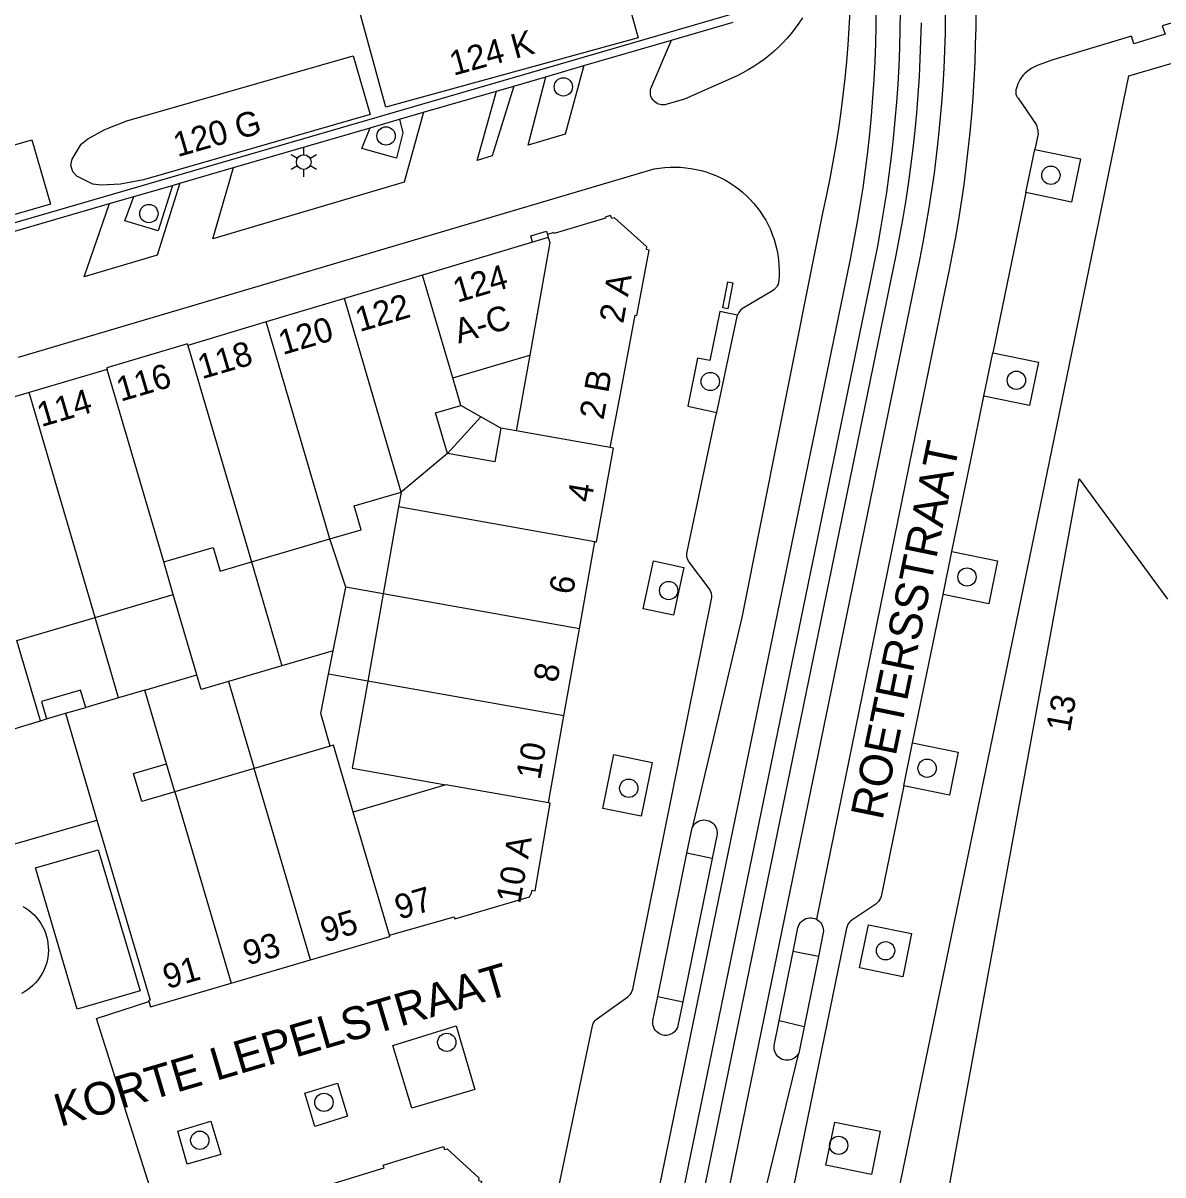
# Model space of a CAD drawing. Extents: x 122462 to 123306, y 485548 to 486417.
# Drawn here: x 122505.2 to 122575, y 486288.9 to 486359.4 of the extents above; entities that cross this region are included whole.
import ezdxf

# ---------------------------------------------------------------- set-up
doc = ezdxf.new("R2010")
doc.units = 0
for name, color, linetype in [('B-WE-IE-MEUBILAIR_WEGMEUBILAIR_VERKEERSBORD-S', 7, 'Continuous'), ('Level 1', 7, 'Continuous'), ('Level 12', 7, 'Continuous'), ('Level 15', 7, 'Continuous'), ('Level 17', 7, 'Continuous'), ('Level 19', 7, 'Continuous'), ('Level 22', 7, 'Continuous'), ('Level 37', 7, 'Continuous'), ('Level 4', 7, 'Continuous'), ('Level 40', 7, 'Continuous'), ('Level 50', 7, 'Continuous'), ('Level 53', 7, 'Continuous'), ('N werkgrens', 7, 'Continuous'), ('N-WE-GR-BOOM_DOORWORTELBARE RUIMTE-G', 7, 'Continuous')]:
    doc.layers.add(name, color=color, linetype=linetype)

msp = doc.modelspace()

# ---------------------------------------------------------------- linework, layer by layer
at = {"layer": 'Level 1'}
for p, q in [((122537.32, 486346.439), (122537.37, 486346.26)), ((122537.37, 486346.26), (122529.68, 486343.956)), ((122529.68, 486343.956), (122524.89, 486342.521)), ((122524.89, 486342.521), (122520.1, 486341.085)), ((122520.1, 486341.085), (122515.31, 486339.65)), ((122531.528, 486337.658), (122536.238, 486339.039)), ((122536.238, 486339.039), (122535.415, 486334.408)), ((122510.373, 486338.171), (122505.584, 486336.761)), ((122532.025, 486335.965), (122531.528, 486337.658)), ((122505.584, 486336.761), (122500.795, 486335.351)), ((122535.415, 486334.408), (122534.464, 486334.577)), ((122528.37, 486330.66), (122528.21, 486329.762)), ((122528.21, 486329.762), (122527.264, 486324.431)), ((122519.202, 486326.386), (122524, 486327.795)), ((122539.276, 486322.298), (122540.223, 486327.629)), ((122514.416, 486324.396), (122513.83, 486326.394)), ((122509.625, 486322.99), (122514.416, 486324.396)), ((122527.264, 486324.431), (122526.318, 486319.099)), ((122504.835, 486321.584), (122509.625, 486322.99)), ((122538.33, 486316.966), (122539.276, 486322.298)), ((122512.671, 486318.547), (122511.067, 486318.076)), ((122514.001, 486314.037), (122512.671, 486318.547)), ((122511.067, 486318.076), (122509.055, 486317.486)), ((122506.656, 486316.782), (122507.808, 486317.12)), ((122507.808, 486317.12), (122509.741, 486310.586)), ((122537.383, 486311.635), (122538.33, 486316.966)), ((122524.025, 486315.116), (122519.363, 486313.741)), ((122519.363, 486313.741), (122514.51, 486312.311)), ((122531.1, 486312.751), (122525.424, 486311.077)), ((122517.964, 486300.597), (122522.817, 486302.028))]:
    msp.add_line(p, q, dxfattribs=at)
for points in [[(122541.171, 486333.386), (122541.732, 486336.354), (122542.702, 486341.488), (122542.799, 486341.469), (122543.549, 486345.469), (122543.38, 486345.51), (122543.4, 486345.679), (122541.429, 486347.459), (122541.26, 486347.42), (122541.189, 486347.6), (122540.856, 486347.5), (122540.876, 486347.433), (122537.727, 486346.489), (122537.707, 486346.556), (122537.32, 486346.439)], [(122515.31, 486339.65), (122515.279, 486339.749), (122510.34, 486338.279), (122510.373, 486338.171)], [(122531.207, 486333.029), (122530.478, 486335.512), (122532.025, 486335.965)], [(122534.464, 486334.577), (122534.099, 486332.516), (122531.207, 486333.029)], [(122540.223, 486327.629), (122540.33, 486327.61), (122541.37, 486333.35), (122541.171, 486333.386)], [(122566.553, 486269.322), (122558.125, 486267.38), (122560.961, 486282.861), (122569.869, 486331.482), (122575.278, 486324.101)], [(122524, 486327.795), (122525.92, 486328.359), (122525.492, 486329.817), (122528.37, 486330.66)], [(122513.83, 486326.394), (122516.855, 486327.281), (122517.283, 486325.823), (122519.202, 486326.386)], [(122526.318, 486319.099), (122525.371, 486313.768), (122531.1, 486312.751)], [(122509.055, 486317.486), (122508.743, 486318.541), (122506.344, 486317.837), (122506.656, 486316.782)], [(122525.424, 486311.077), (122524.216, 486315.172), (122524.025, 486315.116)], [(122514.51, 486312.311), (122512.496, 486311.717), (122511.987, 486313.443), (122514.001, 486314.037)], [(122527.646, 486303.541), (122531.621, 486304.664), (122531.66, 486304.529), (122536.229, 486305.89), (122536.35, 486306.13), (122536.379, 486306.289), (122536.57, 486306.249), (122537.479, 486311.62), (122537.383, 486311.635)], [(122509.741, 486310.586), (122513.003, 486299.564), (122512.902, 486299.534), (122512.922, 486299.468)], [(122522.817, 486302.028), (122527.67, 486303.459), (122527.646, 486303.541)], [(122512.922, 486299.468), (122513.019, 486299.14), (122517.964, 486300.597)], [(122519.559, 486286.91), (122527.317, 486289.297), (122527.269, 486289.449), (122530.959, 486290.59), (122531.009, 486290.409), (122531.189, 486290.459), (122533.12, 486288.679), (122533.098, 486288.51), (122533.289, 486288.479), (122532.58, 486284.679), (122532.48, 486284.697)]]:
    msp.add_lwpolyline(points, dxfattribs=at)
at = {"layer": 'Level 12'}
for points in [[(122527.432, 486354.231), (122525.767, 486360.272), (122541.208, 486364.529), (122542.873, 486358.488), (122527.432, 486354.231)], [(122510.001, 486349.461), (122509.481, 486349.527), (122508.516, 486350.006), (122508.264, 486350.28), (122508.151, 486350.673), (122508.218, 486351.044), (122508.781, 486351.963), (122509.186, 486352.294), (122510.215, 486352.867), (122511.564, 486353.395), (122525.432, 486357.384), (122526.469, 486353.78), (122512.601, 486349.791), (122511.177, 486349.522), (122510.001, 486349.461)], [(122496.33, 486345.23), (122495.189, 486349.168), (122505.755, 486352.228), (122506.896, 486348.29), (122496.33, 486345.23)]]:
    msp.add_lwpolyline(points, dxfattribs=at)
at = {"layer": 'Level 15'}
for p, q in [((122539.553, 486356.775), (122544.919, 486358.335)), ((122537.226, 486356.098), (122539.553, 486356.775)), ((122535.267, 486355.528), (122537.226, 486356.098)), ((122529.736, 486353.919), (122534.194, 486355.216)), ((122534.194, 486355.216), (122535.267, 486355.528)), ((122526.474, 486352.971), (122528.261, 486353.49)), ((122528.261, 486353.49), (122529.736, 486353.919)), ((122518.109, 486350.538), (122526.474, 486352.971)), ((122514.812, 486349.579), (122518.109, 486350.538)), ((122511.994, 486348.759), (122514.357, 486349.447)), ((122514.357, 486349.447), (122514.812, 486349.579)), ((122510.508, 486348.327), (122511.994, 486348.759))]:
    msp.add_line(p, q, dxfattribs=at)
for points in [[(122548.544, 486359.909), (122503.438, 486346.792), (122462.03, 486334.493)], [(122544.919, 486358.335), (122548.683, 486359.429)], [(122502.076, 486345.866), (122502.828, 486346.089), (122503.579, 486346.312), (122510.508, 486348.327)]]:
    msp.add_lwpolyline(points, dxfattribs=at)
at = {"layer": 'Level 17'}
for p, q in [((122566.614, 486349.002), (122567.159, 486351.647)), ((122566.614, 486349.002), (122564.591, 486339.187)), ((122564.046, 486336.542), (122564.591, 486339.187)), ((122561.543, 486324.39), (122562.088, 486327.035)), ((122559.678, 486315.317), (122561.543, 486324.39)), ((122559.138, 486312.672), (122559.678, 486315.317)), ((122545.865, 486308.554), (122546.186, 486310.117)), ((122544.072, 486299.774), (122545.865, 486308.554)), ((122547.404, 486308.237), (122545.865, 486308.554)), ((122547.404, 486308.237), (122545.614, 486299.461)), ((122551.507, 486298.285), (122552.359, 486302.529)), ((122553.914, 486302.235), (122552.359, 486302.529)), ((122553.914, 486302.235), (122553.045, 486297.916)), ((122544.072, 486299.774), (122545.614, 486299.461)), ((122553.045, 486297.916), (122551.507, 486298.285)), ((122553.045, 486297.916), (122552.72, 486296.32))]:
    msp.add_line(p, q, dxfattribs=at)
for points in [[(122555.834, 486360.108), (122555.78, 486359.078), (122555.71, 486358.049), (122555.625, 486357.02), (122555.525, 486355.993), (122555.411, 486354.968), (122555.281, 486353.944), (122555.136, 486352.923), (122554.975, 486351.903), (122554.8, 486350.887), (122554.611, 486349.872), (122554.406, 486348.861), (122554.186, 486347.853), (122551.549, 486334.654), (122549.219, 486322.989), (122546.186, 486310.117)], [(122563.553, 486360.204), (122563.542, 486359.128), (122563.517, 486358.052), (122563.478, 486356.976), (122563.425, 486355.901), (122563.357, 486354.827), (122563.275, 486353.754), (122563.179, 486352.682), (122563.069, 486351.611), (122562.945, 486350.542), (122562.806, 486349.474), (122562.653, 486348.409), (122562.486, 486347.346), (122562.305, 486346.284), (122562.11, 486345.226), (122561.901, 486344.17), (122561.678, 486343.117), (122559.661, 486333.249), (122553.787, 486304.513)], [(122577.883, 486360.063), (122574.965, 486359.208), (122575.137, 486358.702), (122573.216, 486358.114), (122573.072, 486358.574), (122568.26, 486357.129), (122567.304, 486356.786), (122567.139, 486356.713), (122566.98, 486356.626), (122566.828, 486356.527), (122566.686, 486356.417), (122566.552, 486356.295), (122566.428, 486356.163), (122566.316, 486356.021), (122566.241, 486355.904), (122566.176, 486355.782), (122566.12, 486355.655), (122566.074, 486355.524), (122566.039, 486355.39), (122566.008, 486355.302), (122565.993, 486355.21), (122565.993, 486355.116), (122566.008, 486355.024), (122566.038, 486354.936), (122566.082, 486354.854), (122566.139, 486354.78), (122567.234, 486353.178), (122567.279, 486353.069), (122567.314, 486352.956), (122567.339, 486352.841), (122567.353, 486352.724), (122567.357, 486352.606), (122567.159, 486351.647)], [(122552.937, 486359.695), (122552.722, 486359.373), (122552.495, 486359.061), (122552.255, 486358.758), (122552.004, 486358.464), (122551.741, 486358.181), (122551.468, 486357.909), (122551.183, 486357.647), (122550.889, 486357.397), (122550.585, 486357.159), (122550.271, 486356.933), (122549.949, 486356.719), (122549.619, 486356.519), (122549.281, 486356.332), (122548.936, 486356.158), (122545.715, 486354.725), (122544.502, 486354.378), (122544.405, 486354.37), (122544.309, 486354.375), (122544.213, 486354.392), (122544.121, 486354.42), (122544.033, 486354.46), (122543.95, 486354.51), (122543.874, 486354.571), (122543.805, 486354.642), (122543.746, 486354.721), (122543.698, 486354.808), (122543.66, 486354.899), (122543.635, 486354.995), (122543.622, 486355.093), (122543.622, 486355.192), (122543.635, 486355.29), (122543.66, 486355.386), (122544.919, 486358.335)], [(122557.112, 486261.311), (122555.258, 486270.655), (122557.913, 486283.48), (122564.031, 486313.025), (122567.907, 486331.822), (122572.924, 486356.15), (122577.242, 486357.411)], [(122539.553, 486356.775), (122538.413, 486352.573), (122536.141, 486351.9), (122537.226, 486356.098)], [(122535.267, 486355.528), (122533.944, 486351.249), (122533.01, 486350.972), (122534.194, 486355.216)], [(122529.736, 486353.919), (122528.551, 486349.65), (122516.837, 486346.178), (122518.109, 486350.538)], [(122528.261, 486353.49), (122528.477, 486352.658), (122528.071, 486351.113), (122525.968, 486351.702), (122526.474, 486352.971)], [(122567.159, 486351.647), (122569.949, 486351.072), (122569.404, 486348.426), (122566.614, 486349.002)], [(122504.943, 486338.93), (122543.859, 486350.456), (122544.512, 486350.537), (122544.832, 486350.559), (122545.152, 486350.564), (122545.472, 486350.554), (122545.791, 486350.527), (122546.108, 486350.485), (122546.423, 486350.427), (122546.734, 486350.353), (122547.042, 486350.264), (122547.344, 486350.159), (122547.641, 486350.04), (122547.932, 486349.906), (122548.215, 486349.757), (122548.491, 486349.595), (122548.759, 486349.418), (122549.017, 486349.229), (122549.265, 486349.027), (122549.503, 486348.813), (122549.73, 486348.588), (122549.946, 486348.351), (122550.149, 486348.104), (122550.34, 486347.847), (122550.518, 486347.581), (122550.682, 486347.306), (122550.832, 486347.023), (122550.968, 486346.734), (122551.089, 486346.437), (122551.196, 486346.135), (122551.287, 486345.829), (122551.363, 486345.518), (122551.423, 486345.203), (122551.467, 486344.886), (122551.496, 486344.567), (122551.508, 486344.248), (122551.505, 486343.927), (122551.485, 486343.608), (122551.469, 486343.5), (122551.438, 486343.396), (122551.393, 486343.297), (122551.335, 486343.205), (122551.265, 486343.121), (122551.184, 486343.048), (122551.094, 486342.987), (122549.312, 486341.935), (122549.233, 486341.881), (122549.16, 486341.819), (122549.096, 486341.748), (122549.04, 486341.67), (122548.994, 486341.586), (122548.959, 486341.497)], [(122514.812, 486349.579), (122513.434, 486345.17), (122508.95, 486343.841), (122510.508, 486348.327)], [(122514.357, 486349.447), (122513.483, 486346.658), (122511.444, 486347.264), (122511.994, 486348.759)], [(122548.959, 486341.497), (122547.881, 486341.727), (122547.257, 486338.723), (122546.516, 486338.864), (122545.92, 486335.921), (122547.686, 486335.545)], [(122547.686, 486335.545), (122548.936, 486341.413), (122548.959, 486341.497)], [(122564.591, 486339.187), (122567.382, 486338.612), (122566.837, 486335.967), (122564.046, 486336.542)], [(122562.088, 486327.035), (122563.24, 486332.63), (122564.046, 486336.542)], [(122537.898, 486287.543), (122540.073, 486297.984), (122540.101, 486298.074), (122540.139, 486298.16), (122540.187, 486298.241), (122540.245, 486298.316), (122540.311, 486298.383), (122540.384, 486298.442), (122542.24, 486299.769), (122542.327, 486299.841), (122542.403, 486299.925), (122542.466, 486300.018), (122542.516, 486300.12), (122542.551, 486300.227), (122547.367, 486324.118), (122547.381, 486324.229), (122547.38, 486324.342), (122547.362, 486324.453), (122547.33, 486324.561), (122547.283, 486324.663), (122547.222, 486324.757), (122546.011, 486326.364), (122545.957, 486326.446), (122545.914, 486326.533), (122545.882, 486326.625), (122545.86, 486326.721), (122545.851, 486326.818), (122545.854, 486326.915), (122545.868, 486327.012), (122547.64, 486335.331), (122547.686, 486335.545)], [(122562.088, 486327.035), (122564.88, 486326.46), (122564.335, 486323.815), (122561.543, 486324.39)], [(122545.038, 486323.121), (122543.181, 486323.522), (122543.815, 486326.456), (122545.672, 486326.055), (122545.038, 486323.121)], [(122559.678, 486315.317), (122562.471, 486314.748), (122561.931, 486312.103), (122559.138, 486312.672)], [(122543.063, 486310.821), (122540.712, 486311.302), (122541.386, 486314.594), (122543.737, 486314.113), (122543.063, 486310.821)], [(122559.138, 486312.672), (122557.761, 486305.908), (122557.714, 486305.801), (122557.657, 486305.699), (122557.591, 486305.603), (122557.516, 486305.513), (122557.434, 486305.431), (122555.963, 486304.458), (122555.884, 486304.398), (122555.813, 486304.328), (122555.752, 486304.25), (122555.702, 486304.164), (122555.664, 486304.072), (122555.638, 486303.976), (122551.694, 486284.742)], [(122546.186, 486310.117), (122546.239, 486310.216), (122546.305, 486310.307), (122546.384, 486310.388), (122546.473, 486310.457), (122546.571, 486310.513), (122546.675, 486310.554), (122546.785, 486310.581), (122546.897, 486310.591), (122547.01, 486310.586), (122547.12, 486310.566), (122547.227, 486310.53), (122547.327, 486310.479), (122547.42, 486310.415), (122547.502, 486310.338), (122547.572, 486310.25), (122547.629, 486310.153), (122547.671, 486310.048), (122547.699, 486309.939), (122547.71, 486309.827), (122547.706, 486309.715), (122547.404, 486308.237)], [(122552.359, 486302.529), (122552.653, 486303.993), (122552.686, 486304.098), (122552.733, 486304.198), (122552.794, 486304.29), (122552.867, 486304.373), (122552.951, 486304.445), (122553.044, 486304.505), (122553.144, 486304.551), (122553.25, 486304.582), (122553.359, 486304.599), (122553.47, 486304.6), (122553.579, 486304.586), (122553.686, 486304.557), (122553.787, 486304.513)], [(122553.787, 486304.513), (122553.88, 486304.457), (122553.964, 486304.389), (122554.039, 486304.31), (122554.101, 486304.221), (122554.151, 486304.124), (122554.187, 486304.022), (122554.209, 486303.916), (122554.217, 486303.807), (122554.209, 486303.699), (122553.914, 486302.235)], [(122559.07, 486300.987), (122556.427, 486301.535), (122556.974, 486304.178), (122559.617, 486303.631), (122559.07, 486300.987)], [(122545.614, 486299.461), (122545.312, 486297.98), (122545.276, 486297.878), (122545.227, 486297.782), (122545.165, 486297.693), (122545.091, 486297.614), (122545.007, 486297.545), (122544.915, 486297.489), (122544.815, 486297.446), (122544.711, 486297.417), (122544.604, 486297.402), (122544.496, 486297.403), (122544.388, 486297.418), (122544.284, 486297.448), (122544.185, 486297.491), (122544.093, 486297.548), (122544.01, 486297.617), (122543.936, 486297.697), (122543.875, 486297.786), (122543.826, 486297.882), (122543.791, 486297.985), (122543.77, 486298.091), (122543.764, 486298.199), (122543.773, 486298.307), (122544.072, 486299.774)], [(122529.014, 486292.949), (122527.85, 486296.787), (122531.733, 486297.987), (122532.882, 486294.079), (122529.014, 486292.949)], [(122552.72, 486296.32), (122552.658, 486296.225), (122552.585, 486296.138), (122552.501, 486296.062), (122552.408, 486295.996), (122552.308, 486295.943), (122552.202, 486295.903), (122552.099, 486295.882), (122551.994, 486295.874), (122551.889, 486295.88), (122551.786, 486295.9), (122551.687, 486295.934), (122551.592, 486295.98), (122551.505, 486296.039), (122551.426, 486296.108), (122551.358, 486296.188), (122551.3, 486296.276), (122551.254, 486296.37), (122551.221, 486296.47), (122551.202, 486296.573), (122551.197, 486296.678), (122551.205, 486296.783), (122551.507, 486298.285)], [(122542.925, 486250), (122542.93, 486250.08), (122542.987, 486250.683), (122543.058, 486251.285), (122543.145, 486251.885), (122543.246, 486252.483), (122543.363, 486253.078), (122543.494, 486253.67), (122548.947, 486280.821), (122549.986, 486285.089), (122552.72, 486296.32)], [(122523.085, 486291.83), (122522.465, 486293.864), (122524.47, 486294.48), (122525.09, 486292.446), (122523.085, 486291.83)], [(122515.266, 486289.508), (122514.69, 486291.542), (122516.717, 486292.153), (122517.316, 486290.113), (122515.266, 486289.508)], [(122557.162, 486288.885), (122554.362, 486289.45), (122554.907, 486292.094), (122557.698, 486291.532), (122557.162, 486288.885)]]:
    msp.add_lwpolyline(points, dxfattribs=at)
at = {"layer": 'Level 19'}
for p, q in [((122533.245, 486335.271), (122532.025, 486335.965)), ((122531.207, 486333.029), (122533.245, 486335.271)), ((122534.464, 486334.577), (122533.245, 486335.271)), ((122524.97, 486324.838), (122524, 486327.795)), ((122519.202, 486326.386), (122521.07, 486320.023)), ((122524.199, 486320.941), (122524.97, 486324.838)), ((122527.264, 486324.431), (122524.97, 486324.838)), ((122515.858, 486319.482), (122514.416, 486324.396)), ((122511.067, 486318.076), (122509.625, 486322.99)), ((122506.279, 486316.661), (122504.835, 486321.584)), ((122524.199, 486320.941), (122521.07, 486320.023)), ((122523.919, 486319.525), (122524.199, 486320.941)), ((122521.07, 486320.023), (122517.794, 486319.062)), ((122512.671, 486318.547), (122515.858, 486319.482)), ((122517.794, 486319.062), (122519.363, 486313.741)), ((122526.318, 486319.099), (122523.919, 486319.525)), ((122514.51, 486312.311), (122514.001, 486314.037))]:
    msp.add_line(p, q, dxfattribs=at)
for points in [[(122517.794, 486319.062), (122516.125, 486318.572), (122515.858, 486319.482)], [(122524.025, 486315.116), (122523.439, 486317.102), (122523.919, 486319.525)], [(122508.535, 486299.016), (122505.978, 486307.655), (122509.821, 486308.767), (122512.378, 486300.127), (122508.535, 486299.016)]]:
    msp.add_lwpolyline(points, dxfattribs=at)
at = {"layer": 'Level 22'}
msp.add_lwpolyline([(122505.209, 486305.3), (122505.396, 486305.187), (122505.574, 486305.062), (122505.743, 486304.923), (122505.902, 486304.773), (122506.049, 486304.612), (122506.184, 486304.441), (122506.306, 486304.26), (122506.416, 486304.071), (122506.511, 486303.875), (122506.592, 486303.672), (122506.658, 486303.464), (122506.708, 486303.252), (122506.744, 486303.036), (122506.763, 486302.819), (122506.767, 486302.601), (122506.755, 486302.383), (122506.728, 486302.166), (122506.685, 486301.952), (122506.627, 486301.742), (122506.553, 486301.536), (122506.465, 486301.337), (122506.363, 486301.144), (122506.247, 486300.959), (122506.118, 486300.783), (122505.977, 486300.616), (122505.824, 486300.461), (122505.66, 486300.316), (122505.487, 486300.184), (122505.304, 486300.065), (122505.113, 486299.959)], dxfattribs=at)
at = {"layer": 'Level 37'}
for points in [[(122537.028, 486253.319), (122555.873, 486344.927), (122556.089, 486346.015), (122556.289, 486347.106), (122556.473, 486348.2), (122556.641, 486349.296), (122556.794, 486350.395), (122556.931, 486351.495), (122557.052, 486352.598), (122557.157, 486353.702), (122557.246, 486354.808), (122557.319, 486355.914), (122557.376, 486357.022), (122557.418, 486358.13), (122557.443, 486359.186), (122557.454, 486360.241)], [(122538.497, 486253.107), (122557.323, 486344.629), (122557.54, 486345.72), (122557.741, 486346.814), (122557.926, 486347.911), (122558.096, 486349.011), (122558.25, 486350.112), (122558.389, 486351.216), (122558.512, 486352.322), (122558.619, 486353.429), (122558.711, 486354.538), (122558.786, 486355.648), (122558.846, 486356.759), (122558.89, 486357.87), (122558.918, 486358.983), (122558.931, 486360.095)], [(122541.836, 486255.797), (122560.112, 486344.884), (122560.321, 486345.941), (122560.516, 486347.001), (122560.696, 486348.063), (122560.861, 486349.128), (122561.011, 486350.194), (122561.147, 486351.263), (122561.268, 486352.334), (122561.374, 486353.406), (122561.466, 486354.479), (122561.542, 486355.554), (122561.604, 486356.63), (122561.651, 486357.706), (122561.682, 486358.783), (122561.7, 486359.86)], [(122540.388, 486256.1), (122558.662, 486345.182), (122558.875, 486346.262), (122559.073, 486347.345), (122559.256, 486348.431), (122559.422, 486349.519), (122559.573, 486350.61), (122559.709, 486351.702), (122559.828, 486352.797), (122559.932, 486353.893), (122560.02, 486354.99), (122560.092, 486356.089), (122560.148, 486357.188), (122560.189, 486358.289), (122560.214, 486359.389)]]:
    msp.add_lwpolyline(points, dxfattribs=at)
at = {"layer": 'Level 4'}
for p, q in [((122531.528, 486337.658), (122529.68, 486343.956)), ((122528.37, 486330.66), (122524.89, 486342.521)), ((122524, 486327.795), (122520.1, 486341.085)), ((122515.31, 486339.65), (122519.202, 486326.386)), ((122513.83, 486326.394), (122510.373, 486338.171)), ((122509.625, 486322.99), (122505.584, 486336.761)), ((122541.171, 486333.386), (122535.415, 486334.408)), ((122531.207, 486333.029), (122528.37, 486330.66)), ((122540.223, 486327.629), (122528.21, 486329.762)), ((122539.276, 486322.298), (122527.264, 486324.431)), ((122538.33, 486316.966), (122526.318, 486319.099)), ((122507.808, 486317.12), (122509.055, 486317.486)), ((122522.817, 486302.028), (122519.363, 486313.741)), ((122537.383, 486311.635), (122531.1, 486312.751)), ((122514.51, 486312.311), (122517.964, 486300.597)), ((122527.646, 486303.541), (122525.424, 486311.077))]:
    msp.add_line(p, q, dxfattribs=at)
msp.add_lwpolyline([(122537.37, 486346.26), (122537.465, 486345.953), (122536.238, 486339.039)], dxfattribs=at)
at = {"layer": 'Level 40'}
for points in [[(122536.412, 486345.973), (122536.298, 486346.357), (122537.256, 486346.644), (122537.32, 486346.439)], [(122548.372, 486341.893), (122548.057, 486341.953), (122548.358, 486343.547), (122548.673, 486343.487), (122548.372, 486341.893)]]:
    msp.add_lwpolyline(points, dxfattribs=at)
at = {"layer": 'Level 50'}
for p, q in [((122522.012, 486351.098), (122521.622, 486351.323)), ((122522.402, 486351.323), (122522.402, 486351.773)), ((122523.181, 486351.323), (122522.791, 486351.098)), ((122522.012, 486350.648), (122521.622, 486350.423)), ((122523.181, 486350.423), (122522.791, 486350.648)), ((122522.402, 486349.973), (122522.402, 486350.423))]:
    msp.add_line(p, q, dxfattribs=at)
msp.add_circle((122522.402, 486350.873), 0.45, dxfattribs=at)
at = {"layer": 'Level 53'}
for centre in [(122538.295, 486355.475), (122527.443, 486352.473), (122568.142, 486350.065), (122512.921, 486347.719), (122547.289, 486337.436), (122566.032, 486337.511), (122563.01, 486325.466), (122544.745, 486324.637), (122560.567, 486313.758), (122542.301, 486312.533), (122558.021, 486302.582), (122531.159, 486296.976), (122523.639, 486293.304), (122516.038, 486290.978), (122555.152, 486290.667)]:
    msp.add_circle(centre, 0.56, dxfattribs=at)
at = {"layer": 'N werkgrens'}
for p, q in [((122506.279, 486316.661), (122506.656, 486316.782)), ((122501.5, 486315.222), (122506.279, 486316.661)), ((122462.03, 486296.791), (122509.741, 486310.586))]:
    msp.add_line(p, q, dxfattribs=at)
msp.add_lwpolyline([(122513.879, 486285.284), (122509.718, 486298.443), (122512.922, 486299.468)], dxfattribs=at)

# ---------------------------------------------------------------- texts
at = {"layer": 'B-WE-IE-MEUBILAIR_WEGMEUBILAIR_VERKEERSBORD-S'}
for s, rotation, p in [('124 K', 15.41324, (122531.571, 486356.15)), ('120 G', 16.04738, (122514.675, 486351.168)), ('124', 16.3905, (122531.8, 486342.253)), ('2 A', 79.93082, (122541.958, 486340.943)), ('122', 16.3905, (122525.825, 486340.463)), ('A-C', 16.68042, (122531.879, 486339.75)), ('120', 16.3905, (122521.118, 486339.052)), ('118', 16.3905, (122516.173, 486337.571)), ('116', 16.3905, (122511.195, 486336.195)), ('2 B', 79.93082, (122540.746, 486335.045)), ('114', 16.3905, (122506.335, 486334.639)), ('4', 79.93082, (122540.001, 486329.981)), ('6', 79.93082, (122538.878, 486324.336)), ('8', 79.93082, (122537.924, 486318.956)), ('13', 79.6173, (122569.305, 486315.915)), ('10', 79.93082, (122536.865, 486313.001)), ('10 A', 79.93082, (122535.648, 486305.417)), ('97', 16.42757, (122528.237, 486304.475)), ('95', 16.42757, (122523.69, 486303.07)), ('93', 16.42757, (122518.948, 486301.672)), ('91', 16.42757, (122514.043, 486300.225))]:
    msp.add_text(s, height=1.5, rotation=rotation, dxfattribs=at).set_placement(p)
at = {"layer": 'N-WE-GR-BOOM_DOORWORTELBARE RUIMTE-G'}
for s, rotation, p in [('ROETERSSTRAAT', 78.38664, (122557.829, 486310.529)), ('KORTE LEPELSTRAAT', 16.43416, (122507.486, 486291.79))]:
    msp.add_text(s, height=2, rotation=rotation, dxfattribs=at).set_placement(p)

doc.saveas('drawing.dxf')
